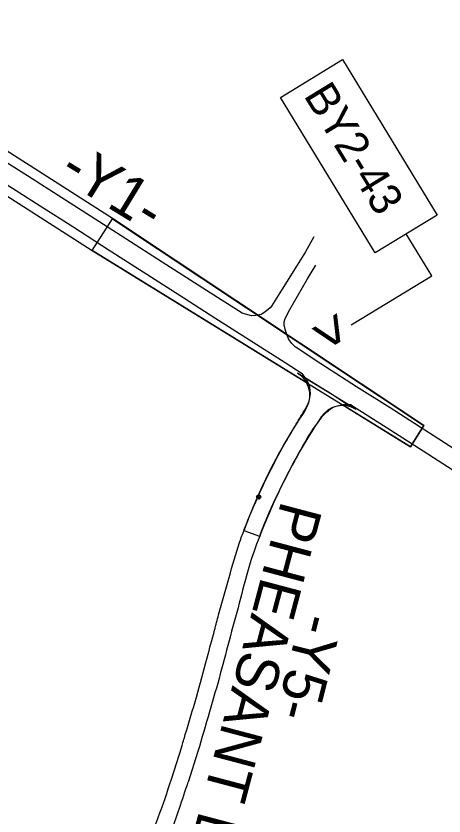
# Model space of a CAD drawing. Extents: x 1771071 to 1790027, y 804210 to 823391.
# Drawn here: x 1783049 to 1783547, y 813286 to 814217 of the extents above; entities that cross this region are included whole.
import ezdxf

# ---------------------------------------------------------------- set-up
doc = ezdxf.new("R2010")
doc.units = 0
for name, color, linetype in [('Default', 7, 'Continuous'), ('Exist Roads EOP', 7, 'Continuous'), ('Old_Level_57', 7, 'Continuous'), ('Prop Conc 5in Monolithic Surface Mount Island', 7, 'Continuous'), ('Prop Horizontal Alignment Tick Large', 7, 'Continuous'), ('Proposed Right of Way Monument PSD Text', 7, 'Continuous'), ('Scratch_Level_1', 7, 'Continuous'), ('Scratch_Level_7', 7, 'Continuous'), ('Scratch_Level_8', 7, 'Continuous')]:
    doc.layers.add(name, color=color, linetype=linetype)

msp = doc.modelspace()

# ---------------------------------------------------------------- linework, layer by layer
at = {"layer": 'Default'}
msp.add_lwpolyline([(1783428.86, 814165.93), (1783539.27, 813985.22), (1783467.15, 813941.16), (1783356.74, 814121.87)], close=True, dxfattribs=at)
msp.add_lwpolyline([(1783439.27, 813857.45), (1783532.84, 813914.65), (1783503.21, 813963.19)], dxfattribs=at)
at = {"layer": 'Exist Roads EOP'}
for p, q in [((1783241.81, 813366.49), (1783229.83, 813328.83)), ((1783260.91, 813361.56), (1783249.48, 813325.74))]:
    msp.add_line(p, q, dxfattribs=at)
for points in [[(1783395.79, 813959.7), (1783385.79, 813942.51), (1783376.4, 813927.05), (1783358.24, 813897.98), (1783346.61, 813879.37), (1783344.7, 813877.44), (1783338.66, 813872.42), (1783334.44, 813869.67), (1783328.07, 813868.25), (1783323.15, 813868.14), (1783318.73, 813868.97), (1783312.39, 813871.24)], [(1783373.85, 813831.77), (1783370.04, 813835.96), (1783366.65, 813840.57), (1783364.39, 813846.14), (1783362.74, 813850.79), (1783361.29, 813857.63), (1783361.17, 813860.89), (1783362.29, 813864.89), (1783367.57, 813875.39), (1783376.61, 813890.73), (1783388.33, 813910.97), (1783397.83, 813926.76)], [(1784007.67, 813426.87), (1783723.29, 813608.26), (1783686.84, 813631.55), (1783644.88, 813658.41), (1783606.03, 813683.1), (1783564.08, 813709.96), (1783524.71, 813734.91), (1783484.4, 813760.83), (1783445.44, 813785.58), (1783403.69, 813812.34), (1783373.86, 813831.78)], [(1783439.03, 813764.33), (1783440.45, 813763.42), (1783480.79, 813737.57), (1783522.95, 813710.96), (1783563.25, 813685.19), (1783599.77, 813661.69), (1783622.02, 813647.62), (1783636.86, 813638.05), (1783675.91, 813613.08), (1783715.47, 813587.8), (1783989.99, 813410.51)]]:
    msp.add_lwpolyline(points, dxfattribs=at)
for points in [[(1781123.7, 814794.56), (1781151.95, 814749.7), (1781175.35, 814711.94), (1781204.02, 814667.22), (1781230.05, 814626.42), (1781255.51, 814585.11), (1781282.93, 814541.39), (1781309.04, 814500.81), (1781338.07, 814453.82), (1781362.44, 814415.66), (1781389.1, 814373.22), (1781417.2, 814328.4), (1781443.82, 814286), (1781469.22, 814245.27), (1781496.33, 814201.88), (1781523.28, 814159.28), (1781551.49, 814114.9), (1781575, 814076.8), (1781602.27, 814034.47), (1781628.68, 813992.42), (1781657.71, 813946.44), (1781682.97, 813906.24), (1781710.54, 813862.11), (1781734.73, 813823.58), (1781763.09, 813779.24), (1781788.41, 813738.38), (1781814.81, 813696.35), (1781842.37, 813653.36), (1781868.91, 813610.68), (1781895.83, 813568.71), (1781924.39, 813523.58), (1781950.61, 813481.8), (1781976.68, 813442.67), (1782004.37, 813401.37), (1782031.99, 813360.12), (1782060.77, 813317.53), (1782089.19, 813276.64), (1782119.2, 813233.31), (1782146.2, 813195.67), (1782175.13, 813155.14), (1782204.07, 813115.4), (1782233.24, 813075.72), (1782263.79, 813034.43), (1782294.03, 812994.29), (1782325.04, 812953.86), (1782354.41, 812916.21), (1782385, 812877.38), (1782417.21, 812837.26), (1782449.43, 812797.65), (1782479.54, 812761.76), (1782513.17, 812720.66), (1782543.05, 812684.98), (1782576.35, 812645.89), (1782608.48, 812608.74), (1782640.69, 812571.37), (1782677.39, 812530.96), (1782710.34, 812494.65), (1782741.2, 812460.83), (1782775.54, 812424.09), (1782810.15, 812387.02), (1782844.36, 812350.73), (1782880.69, 812313.19), (1782914.85, 812277.64), (1782949.87, 812242.16), (1782985.13, 812206.92), (1783022.44, 812170.42), (1783054.86, 812138.57), (1783094.75, 812100.54), (1783130.02, 812066.91), (1783162.74, 812036.24), (1783200.85, 812001.49), (1783239.6, 811965.96), (1783275.52, 811933.35), (1783312.46, 811900.79)], [(1783241.81, 813366.49), (1783246.16, 813381.02), (1783259.06, 813424.58), (1783271.58, 813470.47), (1783280.25, 813502.67), (1783284.89, 813520.4), (1783297.1, 813563.87), (1783309.34, 813604.47), (1783314.75, 813619.5), (1783332.99, 813662.46), (1783354.16, 813705.5), (1783373.78, 813739.77), (1783384.81, 813758.04), (1783390.13, 813768.61), (1783391.62, 813777.33), (1783391.15, 813783.74), (1783389.2, 813790.22), (1783386.57, 813794.66), (1783381.93, 813800.87)], [(1783439.03, 813764.33), (1783431.81, 813764.55), (1783424.43, 813763.45), (1783418.18, 813761.33), (1783411.36, 813756.55), (1783406.61, 813752.09), (1783399.43, 813743.35), (1783390.77, 813730.4), (1783370.6, 813694.51), (1783348.8, 813650.37), (1783336.41, 813621.15), (1783322.52, 813583.49), (1783310.38, 813539.42), (1783298.59, 813495.8), (1783286.9, 813451.66), (1783274.27, 813407.44), (1783260.91, 813361.56)], [(1783229.83, 813328.83), (1783214.33, 813284.24), (1783198.81, 813242.48), (1783184.6, 813205.14), (1783177.01, 813185.51), (1783163.38, 813150.43), (1783158.92, 813144.69), (1783153.27, 813140.22), (1783145.76, 813136.94), (1783137.37, 813135.02), (1783129, 813134.02), (1783114.51, 813133.57), (1783087.67, 813134.85)], [(1783157.14, 813082.62), (1783173.96, 813123.91), (1783190.91, 813165.58), (1783207.2, 813208.66), (1783223.46, 813251.85), (1783239.23, 813295.39), (1783249.48, 813325.74)]]:
    msp.add_spline(points, degree=3, dxfattribs=at)
at = {"layer": 'Prop Conc 5in Monolithic Surface Mount Island'}
for p, q in [((1783376.77, 813801.23), (1783411.47, 813779.84)), ((1783438.47, 813762.21), (1783411.47, 813779.84)), ((1783314.34, 813618.44), (1783332.57, 813611.64))]:
    msp.add_line(p, q, dxfattribs=at)
for centre, radius, start, end in [((1783361.03, 813775.69), 30, 326.3065, 58.35816), ((1783429.18, 813733.69), 30, 58.35816, 146.04752), ((1783955.14, 813379.56), 684.07, 146.3065, 155.30565), ((1783955.14, 813379.56), 664.07, 146.04752, 155.30565)]:
    msp.add_arc(centre, radius, start, end, dxfattribs=at)
for points in [[(1783333.64, 813665.35), (1783333.35, 813664.72), (1783333.07, 813664.1), (1783332.79, 813663.47), (1783332.5, 813662.85), (1783332.22, 813662.22), (1783331.94, 813661.6), (1783331.66, 813660.97), (1783331.38, 813660.34), (1783331.1, 813659.72), (1783330.82, 813659.09), (1783330.55, 813658.46), (1783330.27, 813657.84), (1783329.99, 813657.21), (1783329.72, 813656.58), (1783329.44, 813655.95), (1783329.17, 813655.33), (1783328.9, 813654.7), (1783328.62, 813654.07), (1783328.35, 813653.44), (1783328.08, 813652.81), (1783327.81, 813652.18), (1783327.54, 813651.55), (1783327.27, 813650.92), (1783327, 813650.29), (1783326.73, 813649.66), (1783326.46, 813649.03), (1783326.19, 813648.4), (1783325.92, 813647.76), (1783325.66, 813647.13), (1783325.39, 813646.5), (1783325.13, 813645.87), (1783324.86, 813645.23), (1783324.6, 813644.6), (1783324.34, 813643.97), (1783324.07, 813643.34), (1783323.81, 813642.7), (1783323.55, 813642.07), (1783323.29, 813641.43), (1783323.03, 813640.8), (1783322.77, 813640.16), (1783322.51, 813639.53), (1783322.26, 813638.89), (1783322, 813638.26), (1783321.74, 813637.62), (1783321.49, 813636.99), (1783321.23, 813636.35), (1783320.98, 813635.71), (1783320.72, 813635.08), (1783320.47, 813634.44), (1783320.22, 813633.8), (1783319.96, 813633.17), (1783319.71, 813632.53), (1783319.46, 813631.89), (1783319.21, 813631.25), (1783318.96, 813630.61), (1783318.71, 813629.97), (1783318.46, 813629.34), (1783318.22, 813628.7), (1783317.97, 813628.06), (1783317.72, 813627.42), (1783317.48, 813626.78), (1783317.23, 813626.14), (1783316.99, 813625.5), (1783316.74, 813624.86), (1783316.5, 813624.21), (1783316.26, 813623.57), (1783316.02, 813622.93), (1783315.77, 813622.29), (1783315.53, 813621.65), (1783315.29, 813621.01), (1783315.05, 813620.36), (1783314.82, 813619.72), (1783314.34, 813618.44)], [(1783351.81, 813656.99), (1783351.52, 813656.39), (1783351.24, 813655.78), (1783350.96, 813655.18), (1783350.68, 813654.58), (1783350.4, 813653.97), (1783350.12, 813653.37), (1783349.84, 813652.76), (1783349.57, 813652.16), (1783349.29, 813651.55), (1783349.01, 813650.95), (1783348.74, 813650.34), (1783348.46, 813649.74), (1783348.19, 813649.13), (1783347.91, 813648.52), (1783347.64, 813647.92), (1783347.36, 813647.31), (1783347.09, 813646.7), (1783346.82, 813646.09), (1783346.55, 813645.49), (1783346.28, 813644.88), (1783346.01, 813644.27), (1783345.74, 813643.66), (1783345.47, 813643.05), (1783345.2, 813642.44), (1783344.93, 813641.83), (1783344.67, 813641.22), (1783344.4, 813640.61), (1783344.13, 813640), (1783343.87, 813639.39), (1783343.6, 813638.78), (1783343.34, 813638.17), (1783343.08, 813637.56), (1783342.81, 813636.95), (1783342.55, 813636.33), (1783342.29, 813635.72), (1783342.03, 813635.11), (1783341.77, 813634.5), (1783341.51, 813633.88), (1783341.25, 813633.27), (1783340.99, 813632.66), (1783340.73, 813632.04), (1783340.48, 813631.43), (1783340.22, 813630.81), (1783339.97, 813630.2), (1783339.71, 813629.58), (1783339.45, 813628.97), (1783339.2, 813628.35), (1783338.95, 813627.74), (1783338.69, 813627.12), (1783338.44, 813626.5), (1783338.19, 813625.89), (1783337.94, 813625.27), (1783337.69, 813624.65), (1783337.44, 813624.04), (1783337.19, 813623.42), (1783336.94, 813622.8), (1783336.69, 813622.18), (1783336.45, 813621.57), (1783336.2, 813620.95), (1783335.95, 813620.33), (1783335.71, 813619.71), (1783335.46, 813619.09), (1783335.22, 813618.47), (1783334.97, 813617.85), (1783334.73, 813617.23), (1783334.49, 813616.61), (1783334.25, 813615.99), (1783334.01, 813615.37), (1783333.77, 813614.75), (1783333.53, 813614.13), (1783333.29, 813613.5), (1783333.05, 813612.88), (1783332.57, 813611.64)]]:
    msp.add_spline(points, degree=3, dxfattribs=at)
at = {"layer": 'Prop Horizontal Alignment Tick Large'}
for points in [[(1783328.57, 813657.45), (1783331.57, 813657.45)], [(1783331.57, 813660.45), (1783331.57, 813657.45)], [(1783331.57, 813657.45), (1783334.57, 813657.45)], [(1783331.57, 813657.45), (1783331.57, 813654.45)]]:
    msp.add_lwpolyline(points, dxfattribs=at)
msp.add_circle((1783331.57, 813657.45), 2.34, dxfattribs=at)
at = {"layer": 'Scratch_Level_1'}
for points in [[(1783312.22, 813870.98), (1783270.66, 813897.48), (1783229.11, 813924.07), (1783187.82, 813950.57), (1783145.4, 813977.8), (1783102.46, 814005.18), (1783062.43, 814030.76), (1783037.57, 814046.7), (1783010.11, 814064.34), (1782994.61, 814073.9), (1782968.36, 814091.08), (1782953.36, 814100.59)], [(1782957.05, 814072.69), (1782997.32, 814047.07), (1783033.64, 814023.73), (1783053.56, 814011.03), (1783077.16, 813995.81), (1783116.5, 813970.95), (1783156.27, 813945.27), (1783197.33, 813919.23), (1783238.94, 813892.35), (1783280.65, 813865.79), (1783320.67, 813840.18), (1783362.13, 813813.73), (1783381.93, 813800.87)]]:
    msp.add_lwpolyline(points, dxfattribs=at)
at = {"layer": 'Scratch_Level_8'}
for p, q in [((1783161.34, 813981.02), (1782664.74, 814298.57)), ((1782641.03, 814261.5), (1783137.64, 813943.95)), ((1783137.68, 813943.86), (1783161.38, 813980.92)), ((1783523.77, 813740.34), (1783161.34, 813981.02)), ((1783161.38, 813980.92), (1783523.81, 813740.24)), ((1783137.64, 813943.95), (1783434.73, 813760.88)), ((1783387.41, 813789.97), (1783137.68, 813943.86)), ((1783444.92, 813759.23), (1783376.77, 813801.23)), ((1783508.06, 813715.62), (1783430.08, 813763.67)), ((1783434.73, 813760.88), (1783508.02, 813715.72)), ((1783523.75, 813740.28), (1783508.01, 813715.66)), ((1783508.02, 813715.72), (1783523.77, 813740.34)), ((1783314.34, 813618.44), (1783332.57, 813611.64))]:
    msp.add_line(p, q, dxfattribs=at)
for centre, radius, start, end in [((1783361.03, 813775.69), 30, 326.3065, 58.35816), ((1783429.18, 813733.69), 30, 58.35816, 146.04752), ((1783955.14, 813379.56), 684.07, 146.3065, 155.30565), ((1783955.14, 813379.56), 664.07, 146.04752, 155.30565)]:
    msp.add_arc(centre, radius, start, end, dxfattribs=at)
for points in [[(1783333.64, 813665.35), (1783333.35, 813664.72), (1783333.07, 813664.1), (1783332.79, 813663.47), (1783332.5, 813662.85), (1783332.22, 813662.22), (1783331.94, 813661.6), (1783331.66, 813660.97), (1783331.38, 813660.34), (1783331.1, 813659.72), (1783330.82, 813659.09), (1783330.55, 813658.46), (1783330.27, 813657.84), (1783329.99, 813657.21), (1783329.72, 813656.58), (1783329.44, 813655.95), (1783329.17, 813655.33), (1783328.9, 813654.7), (1783328.62, 813654.07), (1783328.35, 813653.44), (1783328.08, 813652.81), (1783327.81, 813652.18), (1783327.54, 813651.55), (1783327.27, 813650.92), (1783327, 813650.29), (1783326.73, 813649.66), (1783326.46, 813649.03), (1783326.19, 813648.4), (1783325.92, 813647.76), (1783325.66, 813647.13), (1783325.39, 813646.5), (1783325.13, 813645.87), (1783324.86, 813645.23), (1783324.6, 813644.6), (1783324.34, 813643.97), (1783324.07, 813643.34), (1783323.81, 813642.7), (1783323.55, 813642.07), (1783323.29, 813641.43), (1783323.03, 813640.8), (1783322.77, 813640.16), (1783322.51, 813639.53), (1783322.26, 813638.89), (1783322, 813638.26), (1783321.74, 813637.62), (1783321.49, 813636.99), (1783321.23, 813636.35), (1783320.98, 813635.71), (1783320.72, 813635.08), (1783320.47, 813634.44), (1783320.22, 813633.8), (1783319.96, 813633.17), (1783319.71, 813632.53), (1783319.46, 813631.89), (1783319.21, 813631.25), (1783318.96, 813630.61), (1783318.71, 813629.97), (1783318.46, 813629.34), (1783318.22, 813628.7), (1783317.97, 813628.06), (1783317.72, 813627.42), (1783317.48, 813626.78), (1783317.23, 813626.14), (1783316.99, 813625.5), (1783316.74, 813624.86), (1783316.5, 813624.21), (1783316.26, 813623.57), (1783316.02, 813622.93), (1783315.77, 813622.29), (1783315.53, 813621.65), (1783315.29, 813621.01), (1783315.05, 813620.36), (1783314.82, 813619.72), (1783314.34, 813618.44)], [(1783332.57, 813611.64), (1783333.05, 813612.88), (1783333.29, 813613.5), (1783333.53, 813614.13), (1783333.77, 813614.75), (1783334.01, 813615.37), (1783334.25, 813615.99), (1783334.49, 813616.61), (1783334.73, 813617.23), (1783334.97, 813617.85), (1783335.22, 813618.47), (1783335.46, 813619.09), (1783335.71, 813619.71), (1783335.95, 813620.33), (1783336.2, 813620.95), (1783336.45, 813621.57), (1783336.69, 813622.18), (1783336.94, 813622.8), (1783337.19, 813623.42), (1783337.44, 813624.04), (1783337.69, 813624.65), (1783337.94, 813625.27), (1783338.19, 813625.89), (1783338.44, 813626.5), (1783338.69, 813627.12), (1783338.95, 813627.74), (1783339.2, 813628.35), (1783339.45, 813628.97), (1783339.71, 813629.58), (1783339.97, 813630.2), (1783340.22, 813630.81), (1783340.48, 813631.43), (1783340.73, 813632.04), (1783340.99, 813632.66), (1783341.25, 813633.27), (1783341.51, 813633.88), (1783341.77, 813634.5), (1783342.03, 813635.11), (1783342.29, 813635.72), (1783342.55, 813636.33), (1783342.81, 813636.95), (1783343.08, 813637.56), (1783343.34, 813638.17), (1783343.6, 813638.78), (1783343.87, 813639.39), (1783344.13, 813640), (1783344.4, 813640.61), (1783344.67, 813641.22), (1783344.93, 813641.83), (1783345.2, 813642.44), (1783345.47, 813643.05), (1783345.74, 813643.66), (1783346.01, 813644.27), (1783346.28, 813644.88), (1783346.55, 813645.49), (1783346.82, 813646.09), (1783347.09, 813646.7), (1783347.36, 813647.31), (1783347.64, 813647.92), (1783347.91, 813648.52), (1783348.19, 813649.13), (1783348.46, 813649.74), (1783348.74, 813650.34), (1783349.01, 813650.95), (1783349.29, 813651.55), (1783349.57, 813652.16), (1783349.84, 813652.76), (1783350.12, 813653.37), (1783350.4, 813653.97), (1783350.68, 813654.58), (1783350.96, 813655.18), (1783351.24, 813655.78), (1783351.52, 813656.39), (1783351.81, 813656.99)]]:
    msp.add_spline(points, degree=3, dxfattribs=at)

# ---------------------------------------------------------------- texts
at = {"layer": 'Old_Level_57'}
msp.add_text('>', height=46.95, rotation=301.43915, dxfattribs=at).set_placement((1783386.96, 813852.99))
at = {"layer": 'Proposed Right of Way Monument PSD Text'}
msp.add_text('BY2-43', height=37.325, rotation=301.42495, dxfattribs=at).set_placement((1783383.21, 814124.31))
at = {"layer": 'Scratch_Level_7'}
for s, height, rotation, p in [('-Y1-', 49.208, 328.5632, (1783097.33, 814029.67)), ('PHEASANT DR.', 49.2075, 255.16235, (1783358.15, 813654.32)), ('-Y5-', 49.208, 255.67508, (1783381.54, 813524.51))]:
    msp.add_text(s, height=height, rotation=rotation, dxfattribs=at).set_placement(p)

doc.saveas('drawing.dxf')
